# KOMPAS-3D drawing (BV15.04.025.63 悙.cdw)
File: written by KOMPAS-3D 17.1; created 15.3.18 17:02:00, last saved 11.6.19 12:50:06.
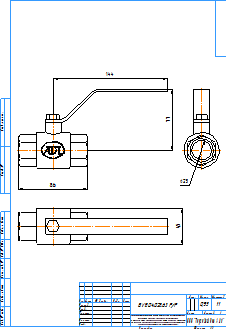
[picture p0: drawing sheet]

Sheet 1: A3, portrait

Title block, sheet 1: name: BV15.04.025.63 Р/Р; material: Внимание! Данный продукт является объектом авторского права ООО «Торговый Дом АДЛ». / Запрещается изменение, копирование, распространение / (в том числе путем копирования на другие сайты и ресурсы в Интернете) / или любое иное использование информации и объектов без предварительного / согласия правообладателя (ООО «Торговый Дом АДЛ»).; mass: 0,95; sheets: 1; organisation: ООО "Торговый дом АДЛ"; sheet format: A3; stored path: \\adlc.lan\data\АДЛ_ПКД\3D-модели\ADL production\Краны шаровые серии BV\BV15\KOMPAS 2D\BV15.04.025.63 РР.cdw

Views: Вид 1, Проекционный вид 2, Проекционный вид 3
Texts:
  kka
  adl
Dimensions and other numbers on the sheet: 86; 144; 77; 25; 45; 1:1; 1; 0,95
